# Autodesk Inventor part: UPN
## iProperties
Author: Jan-Steinar
Shininess: 20.0
PropertySet Name: _Private Model Information
Created: 2001-01
Part Number: UPN
Document SubType Name: Modeling
Designer: Jan-Steinar
Control State: 0
Master: False
Checked Out: False
PropertySet Name: Design Tracking Control
Density: 0.0
Volumn: 0.0
Area: 0.0
PropertySet Name: Model Information
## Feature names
1. Extrusion1
